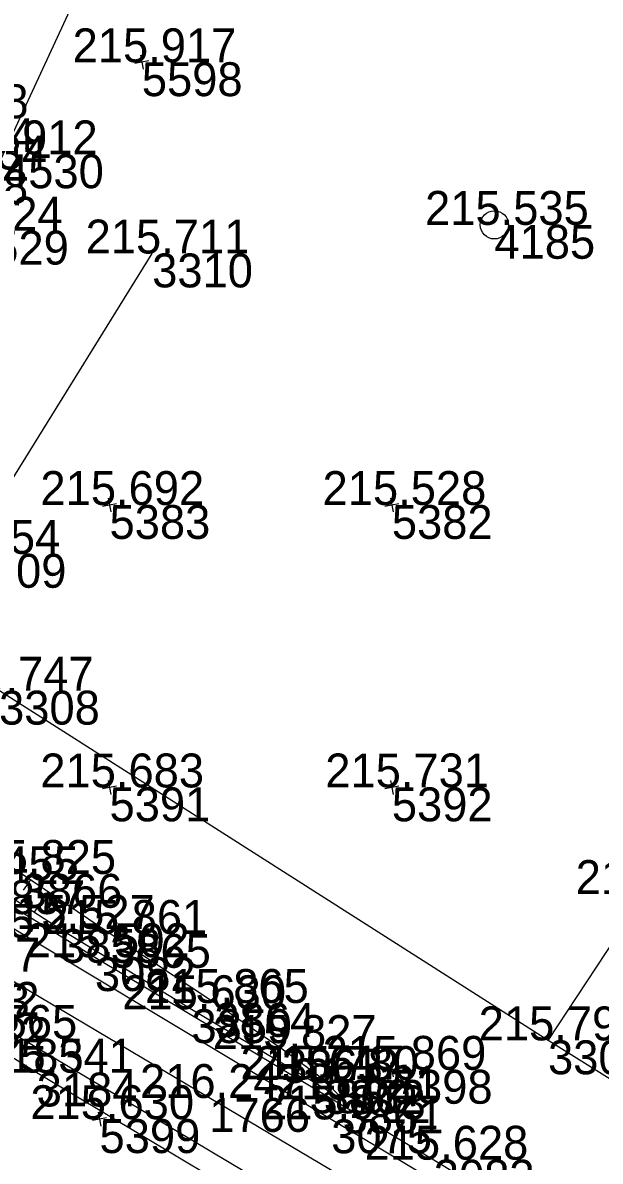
# Model space of a CAD drawing. Extents: x -556590 to -554855, y -1137918 to -1135717.
# Drawn here: x -556453.07 to -556432.62, y -1135813.24 to -1135772.92 of the extents above; entities that cross this region are included whole.
import ezdxf

# ---------------------------------------------------------------- set-up
doc = ezdxf.new("R2010")
doc.units = 0
for name, color, linetype in [('Vrstva 1', 7, 'Continuous'), ('Vrstva 17', 7, 'Continuous'), ('Vrstva 36', 7, 'Continuous'), ('Vrstva 4', 7, 'Continuous'), ('Vrstva 48', 7, 'Continuous'), ('Vrstva 49', 7, 'Continuous'), ('Vrstva 51', 7, 'Continuous'), ('Vrstva 60', 7, 'Continuous'), ('Vrstva 61', 7, 'Continuous')]:
    doc.layers.add(name, color=color, linetype=linetype)

msp = doc.modelspace()

# ---------------------------------------------------------------- linework, layer by layer
at = {"layer": 'Vrstva 1'}
msp.add_lwpolyline([(-556311.953, -1135890.765), (-556321.097, -1135885.34), (-556330.284, -1135879.894), (-556339.612, -1135874.362), (-556348.582, -1135869.039), (-556357.498, -1135863.753), (-556366.106, -1135858.646), (-556374.906, -1135853.428), (-556383.234, -1135848.498), (-556391.876, -1135843.374), (-556400.908, -1135838.017), (-556409.759, -1135832.769), (-556418.646, -1135827.5), (-556428.018, -1135821.939), (-556437.172, -1135816.507), (-556446.468, -1135810.997), (-556456.022, -1135805.326), (-556463.479, -1135800.909), (-556467.629, -1135798.446), (-556476.522, -1135793.164), (-556485.71, -1135787.715), (-556494.622, -1135782.427), (-556503.989, -1135776.868), (-556513.289, -1135771.345)], dxfattribs=at)
at = {"layer": 'Vrstva 17'}
for points in [[(-556434.467, -1135808.957), (-556453.913, -1135796.576), (-556455.096, -1135791.73), (-556448.49, -1135781.094)], [(-556399.18, -1135801.351), (-556412.811, -1135822.277), (-556426.479, -1135813.938), (-556427.784, -1135813.124), (-556434.467, -1135808.957), (-556431.036, -1135803.774), (-556424.263, -1135793.926)]]:
    msp.add_lwpolyline(points, dxfattribs=at)
at = {"layer": 'Vrstva 36'}
msp.add_circle((-556436.367, -1135780.08), 0.5, dxfattribs=at)
at = {"layer": 'Vrstva 4'}
for points in [[(-556423.133, -1135823.118), (-556442.147, -1135811.755), (-556461.606, -1135800.09), (-556462.261, -1135799.671), (-556462.556, -1135799.308), (-556462.656, -1135799.127), (-556461.963, -1135799.074), (-556461.506, -1135799.244), (-556450.518, -1135806.011), (-556438.512, -1135813.182), (-556425.945, -1135820.823)], [(-556429.315, -1135822.957), (-556442.078, -1135815.472), (-556456.395, -1135806.956), (-556460.94, -1135804.337), (-556461.836, -1135803.803), (-556462.329, -1135803.606), (-556462.774, -1135803.562), (-556462.023, -1135804.323), (-556461.425, -1135804.873), (-556460.663, -1135805.387), (-556457.875, -1135806.855), (-556455.835, -1135808.089), (-556454.489, -1135808.903), (-556452.58, -1135810.098), (-556441.444, -1135816.756), (-556425.052, -1135826.406)]]:
    msp.add_lwpolyline(points, dxfattribs=at)
at = {"layer": 'Vrstva 48'}
for p, q in [((-556452.805, -1135803.273), (-556453.055, -1135803.642)), ((-556452.184, -1135803.694), (-556452.674, -1135804.416))]:
    msp.add_line(p, q, dxfattribs=at)
at = {"layer": 'Vrstva 49'}
for p, q in [((-556448.61, -1135774.276), (-556449.102, -1135774.37)), ((-556448.903, -1135774.077), (-556448.809, -1135774.569)), ((-556450.047, -1135789.754), (-556449.953, -1135790.246)), ((-556440.047, -1135789.754), (-556439.953, -1135790.246)), ((-556449.754, -1135789.953), (-556450.246, -1135790.047)), ((-556439.754, -1135789.953), (-556440.246, -1135790.047)), ((-556450.047, -1135799.754), (-556449.953, -1135800.246)), ((-556440.047, -1135799.754), (-556439.953, -1135800.246)), ((-556449.754, -1135799.953), (-556450.246, -1135800.047)), ((-556439.754, -1135799.953), (-556440.246, -1135800.047)), ((-556440.047, -1135809.754), (-556439.953, -1135810.246)), ((-556439.754, -1135809.953), (-556440.246, -1135810.047)), ((-556450.402, -1135811.501), (-556450.308, -1135811.993)), ((-556450.109, -1135811.7), (-556450.601, -1135811.794))]:
    msp.add_line(p, q, dxfattribs=at)
for points in [[(-556441.741, -1135811.05), (-556442.409, -1135810.359), (-556443.888, -1135809.263), (-556446.286, -1135807.633), (-556449.98, -1135805.188), (-556453.114, -1135803.063), (-556456.956, -1135800.565), (-556459.518, -1135798.97), (-556460.709, -1135798.251), (-556461.424, -1135797.985), (-556461.97, -1135798.017), (-556462.305, -1135798.382), (-556462.616, -1135798.772), (-556462.656, -1135799.127)], [(-556462.656, -1135799.127), (-556461.963, -1135799.074), (-556461.506, -1135799.244), (-556458.805, -1135800.652), (-556454.433, -1135803.285), (-556451.748, -1135805.011), (-556447.098, -1135807.853), (-556442.91, -1135810.342), (-556441.741, -1135811.05)]]:
    msp.add_lwpolyline(points, dxfattribs=at)
at = {"layer": 'Vrstva 51'}
msp.add_lwpolyline([(-556445.54, -1135756.137), (-556450.048, -1135762.754), (-556451.807, -1135766.966), (-556456.219, -1135776.305), (-556459.365, -1135783.735), (-556461.698, -1135788.741), (-556462.943, -1135791.573), (-556464.002, -1135793.51), (-556465.359, -1135795.805), (-556466.521, -1135797.535), (-556463.103, -1135799.556), (-556463.142, -1135798.233), (-556461.088, -1135794.653), (-556458.145, -1135788.25), (-556455.011, -1135780.286), (-556453.772, -1135777.583), (-556449.7, -1135768.789), (-556447.521, -1135764.345), (-556442.822, -1135758.037)], dxfattribs=at)
at = {"layer": 'Vrstva 60'}
for p, q in [((-556448.856, -1135774.323), (-556448.856, -1135774.323)), ((-556436.367, -1135780.08), (-556436.367, -1135780.08)), ((-556448.49, -1135781.094), (-556448.49, -1135781.094)), ((-556450, -1135790), (-556450, -1135790)), ((-556440, -1135790), (-556440, -1135790)), ((-556450, -1135800), (-556450, -1135800)), ((-556440, -1135800), (-556440, -1135800)), ((-556451.748, -1135805.011), (-556451.748, -1135805.011)), ((-556449.98, -1135805.188), (-556449.98, -1135805.188)), ((-556450.518, -1135806.011), (-556450.518, -1135806.011)), ((-556447.098, -1135807.853), (-556447.098, -1135807.853)), ((-556446.286, -1135807.633), (-556446.286, -1135807.633)), ((-556434.467, -1135808.957), (-556434.467, -1135808.957)), ((-556443.888, -1135809.263), (-556443.888, -1135809.263)), ((-556452.58, -1135810.098), (-556452.58, -1135810.098)), ((-556440, -1135810), (-556440, -1135810)), ((-556442.91, -1135810.342), (-556442.91, -1135810.342)), ((-556442.409, -1135810.359), (-556442.409, -1135810.359)), ((-556446.468, -1135810.997), (-556446.468, -1135810.997)), ((-556441.741, -1135811.05), (-556441.741, -1135811.05)), ((-556450.355, -1135811.747), (-556450.355, -1135811.747)), ((-556442.147, -1135811.755), (-556442.147, -1135811.755)), ((-556438.512, -1135813.182), (-556438.512, -1135813.182))]:
    msp.add_line(p, q, dxfattribs=at)

# ---------------------------------------------------------------- texts
for s, p in [('5598', (-556448.856, -1135775.523)), ('4154', (-556456.219, -1135777.505)), ('4530', (-556453.772, -1135778.783)), ('418', (-556455.56, -1135779.322)), ('4185', (-556436.367, -1135781.28)), ('4529', (-556455.011, -1135781.486)), ('3310', (-556448.49, -1135782.294)), ('5383', (-556450, -1135791.2)), ('5382', (-556440, -1135791.2)), ('3309', (-556455.096, -1135792.93)), ('3308', (-556453.913, -1135797.776)), ('5391', (-556450, -1135801.2)), ('5392', (-556440, -1135801.2)), ('3866', (-556453.114, -1135804.263)), ('3857', (-556454.433, -1135804.485)), ('3858', (-556451.748, -1135806.211)), ('1767', (-556456.022, -1135806.526)), ('3865', (-556449.98, -1135806.388)), ('3082', (-556450.518, -1135807.211)), ('3173', (-556456.395, -1135808.156)), ('3859', (-556447.098, -1135809.053)), ('3864', (-556446.286, -1135808.833)), ('3182', (-556455.835, -1135809.289)), ('3183', (-556454.489, -1135810.103)), ('3305', (-556434.467, -1135810.157)), ('3863', (-556443.888, -1135810.463)), ('3184', (-556452.58, -1135811.298)), ('3860', (-556442.91, -1135811.542)), ('5398', (-556440, -1135811.2)), ('3862', (-556442.409, -1135811.559)), ('1766', (-556446.468, -1135812.197)), ('3861', (-556441.741, -1135812.25)), ('5399', (-556450.355, -1135812.947)), ('3075', (-556442.147, -1135812.955)), ('3083', (-556438.512, -1135814.382))]:
    msp.add_text(s, height=1.2, dxfattribs=at).set_placement(p)
at = {"layer": 'Vrstva 61'}
for s, p in [('215.917', (-556451.308, -1135774.323)), ('215.828', (-556458.673, -1135776.305)), ('215.912', (-556456.22, -1135777.583)), ('216.034', (-556458.011, -1135778.122)), ('215.535', (-556438.823, -1135780.08)), ('215.924', (-556457.462, -1135780.286)), ('215.711', (-556450.847, -1135781.094)), ('215.692', (-556452.448, -1135790)), ('215.528', (-556442.454, -1135790)), ('215.854', (-556457.547, -1135791.73)), ('215.747', (-556456.365, -1135796.576)), ('215.683', (-556452.452, -1135800)), ('215.731', (-556442.357, -1135800)), ('215.825', (-556455.57, -1135803.063)), ('215.455', (-556456.889, -1135803.285)), ('215.830', (-556433.487, -1135803.774)), ('215.527', (-556454.2, -1135805.011)), ('216.255', (-556458.478, -1135805.326)), ('215.861', (-556452.337, -1135805.188)), ('215.502', (-556452.966, -1135806.011)), ('215.630', (-556449.549, -1135807.853)), ('215.865', (-556448.742, -1135807.633)), ('215.662', (-556458.283, -1135808.089)), ('215.565', (-556456.945, -1135808.903)), ('215.795', (-556436.923, -1135808.957)), ('215.827', (-556446.34, -1135809.263)), ('215.541', (-556454.937, -1135810.098)), ('215.869', (-556442.454, -1135810)), ('215.617', (-556445.362, -1135810.342)), ('215.780', (-556444.86, -1135810.359)), ('216.247', (-556448.92, -1135810.997)), ('215.621', (-556444.098, -1135811.05)), ('215.630', (-556452.806, -1135811.747)), ('215.973', (-556444.599, -1135811.755)), ('215.628', (-556440.966, -1135813.182))]:
    msp.add_text(s, height=1.2, dxfattribs=at).set_placement(p)

doc.saveas('drawing.dxf')
